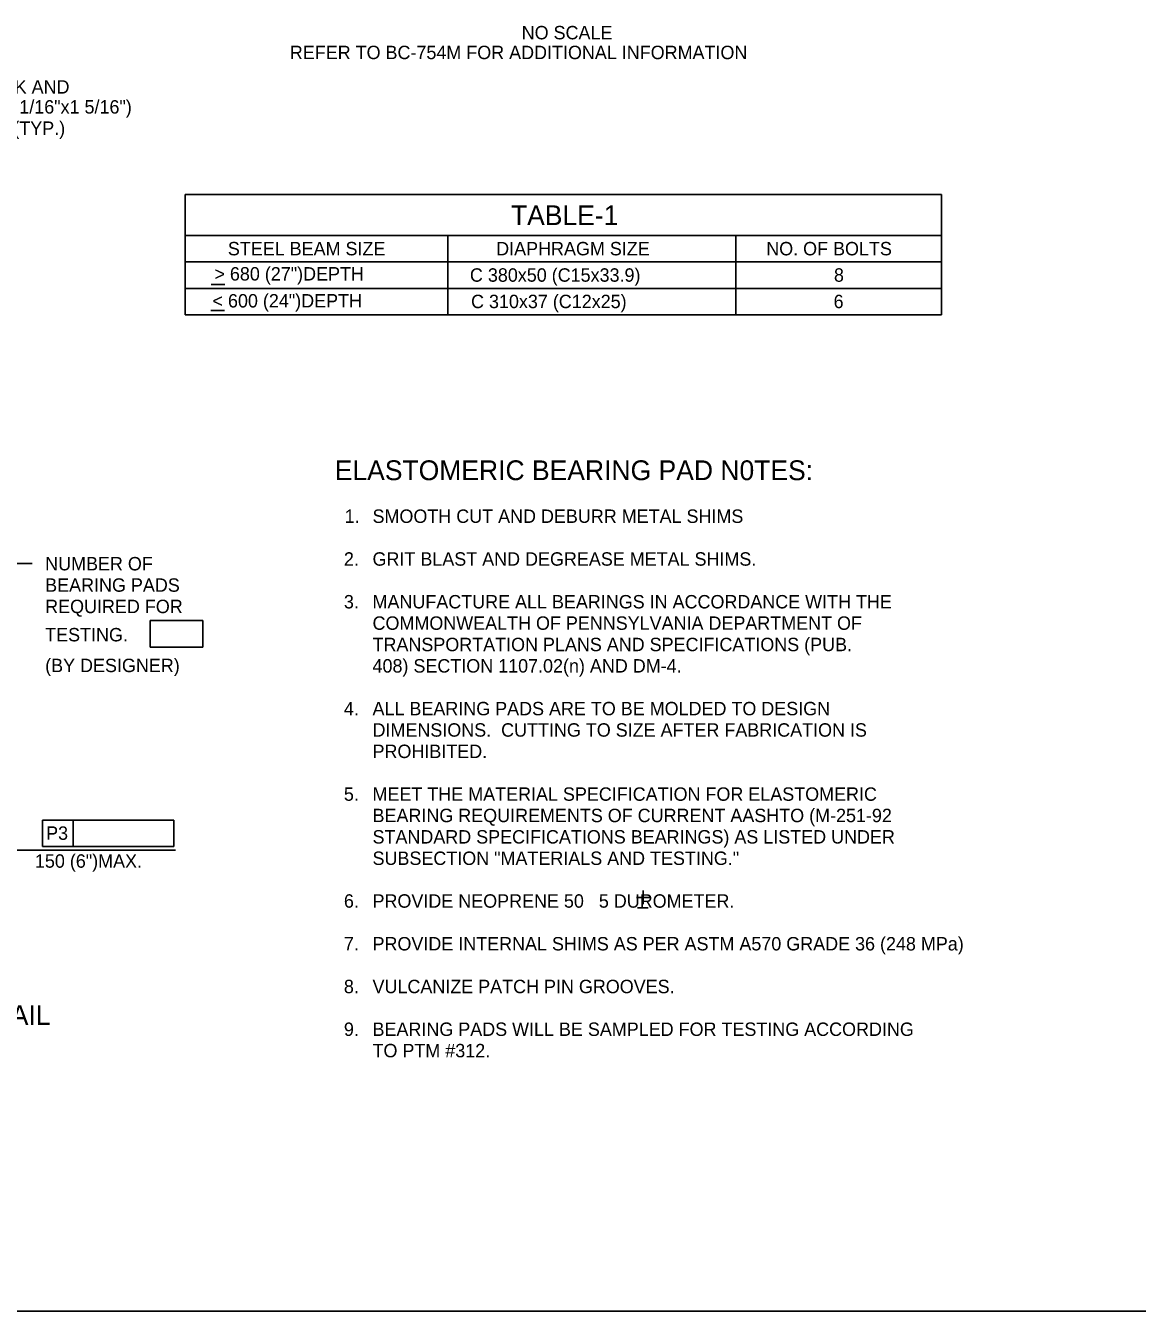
# Model space of a CAD drawing. Extents: x 638175 to 640495, y 294277 to 298435.
# Drawn here: x 639649.2 to 639897.7, y 297262.5 to 297550 of the extents above; entities that cross this region are included whole.
import ezdxf

# ---------------------------------------------------------------- set-up
doc = ezdxf.new("R2010")
doc.units = 0
doc.layers.add('2', color=7, linetype='Continuous')
doc.layers.add('3', color=7, linetype='Continuous')

msp = doc.modelspace()

# ---------------------------------------------------------------- linework, layer by layer
at = {"layer": '2'}
for p, q in [((639647.13, 297429.69), (639650.63, 297429.69)), ((640102.46, 297262.46), (639316.46, 297262.46))]:
    msp.add_line(p, q, dxfattribs=at)
at = {"layer": '3'}
for p, q in [((639684.79, 297512.2), (639853.91, 297512.2)), ((639684.79, 297512.2), (639684.79, 297485.33)), ((639853.91, 297512.2), (639853.91, 297485.33)), ((639684.79, 297503.05), (639853.91, 297503.05)), ((639743.52, 297503.05), (639743.52, 297485.33)), ((639807.93, 297503.05), (639807.93, 297485.33)), ((639684.79, 297497.14), (639853.91, 297497.14)), ((639693.71, 297492.13), (639690.63, 297492.13)), ((639684.79, 297491.24), (639853.91, 297491.24)), ((639693.64, 297486.25), (639690.56, 297486.25)), ((639684.79, 297485.33), (639853.91, 297485.33)), ((639677, 297416.92), (639688.8, 297416.92)), ((639677, 297416.92), (639677, 297411.01)), ((639688.8, 297416.92), (639688.8, 297411.01)), ((639677, 297411.01), (639688.8, 297411.01)), ((639652.89, 297372.32), (639682.29, 297372.32)), ((639652.89, 297366.42), (639652.89, 297372.32)), ((639659.74, 297366.42), (639659.74, 297372.32)), ((639682.29, 297372.32), (639682.29, 297366.42)), ((639645.02, 297365.59), (639682.68, 297365.59)), ((639682.29, 297366.42), (639652.89, 297366.42)), ((639785.72, 297355), (639788.86, 297355)), ((639787.23, 297353.49), (639787.23, 297356.57)), ((639785.96, 297352.71), (639788.31, 297352.71))]:
    msp.add_line(p, q, dxfattribs=at)

# ---------------------------------------------------------------- texts
for s, height, p in [('NO SCALE', 3, (639760.06, 297546.93)), ('REFER TO BC-754M FOR ADDITIONAL INFORMATION', 3, (639708.22, 297542.5)), ('FOR NORTHERN RED OAK AND', 3, (639597.88, 297534.8)), ('RED MAPLE.  27.0x33.3 (1 1/16"x1 5/16")', 3, (639597.78, 297530.33)), ('YELLOW POPLAR. (TYP.)', 3, (639610.05, 297525.56)), ('TABLE-1', 4.429, (639757.66, 297505.38)), ('STEEL BEAM SIZE', 3, (639694.36, 297498.62)), ('DIAPHRAGM SIZE', 3, (639754.36, 297498.62)), ('NO. OF BOLTS', 3, (639814.75, 297498.62)), ('> 680 (27")DEPTH', 3, (639691.36, 297492.99)), ('C 380x50 (C15x33.9)', 3, (639748.49, 297492.72)), ('8', 3, (639829.89, 297492.72)), ('< 600 (24")DEPTH', 3, (639690.93, 297486.96)), ('C 310x37 (C12x25)', 3, (639748.74, 297486.81)), ('6', 3, (639829.81, 297486.81)), ('ELASTOMERIC BEARING PAD N0TES:', 4.4292, (639718.26, 297448.34)), ('1.', 3, (639720.48, 297438.78)), ('SMOOTH CUT AND DEBURR METAL SHIMS', 3, (639726.71, 297438.78)), ('2.', 3, (639720.31, 297429.21)), ('GRIT BLAST AND DEGREASE METAL SHIMS.', 3, (639726.71, 297429.21)), ('NUMBER OF', 3, (639653.51, 297428.16)), ('BEARING PADS', 3, (639653.51, 297423.38)), ('REQUIRED FOR', 3, (639653.51, 297418.6)), ('3.', 3, (639720.31, 297419.65)), ('MANUFACTURE ALL BEARINGS IN ACCORDANCE WITH THE', 3, (639726.71, 297419.65)), ('COMMONWEALTH OF PENNSYLVANIA DEPARTMENT OF', 3, (639726.71, 297414.87)), ('TESTING.', 3, (639653.51, 297412.28)), ('TRANSPORTATION PLANS AND SPECIFICATIONS (PUB.', 3, (639726.71, 297410.09)), ('(BY DESIGNER)', 3, (639653.51, 297405.41)), ('408) SECTION 1107.02(n) AND DM-4.', 3, (639726.71, 297405.31)), ('4.', 3, (639720.31, 297395.75)), ('ALL BEARING PADS ARE TO BE MOLDED TO DESIGN', 3, (639726.71, 297395.75)), ('DIMENSIONS.  CUTTING TO SIZE AFTER FABRICATION IS', 3, (639726.71, 297390.97)), ('PROHIBITED.', 3, (639726.71, 297386.19)), ('5.', 3, (639720.31, 297376.63)), ('MEET THE MATERIAL SPECIFICATION FOR ELASTOMERIC', 3, (639726.71, 297376.63)), ('BEARING REQUIREMENTS OF CURRENT AASHTO (M-251-92', 3, (639726.71, 297371.85)), ('P3', 3, (639653.72, 297367.9)), ('STANDARD SPECIFICATIONS BEARINGS) AS LISTED UNDER', 3, (639726.71, 297367.07)), ('SUBSECTION "MATERIALS AND TESTING."', 3, (639726.71, 297362.28)), ('150 (6")MAX.', 3, (639651.22, 297361.66)), ('6.', 3, (639720.31, 297352.72)), ('PROVIDE NEOPRENE 50   5 DUROMETER.', 3, (639726.71, 297352.72)), ('7.', 3, (639720.31, 297343.16)), ('PROVIDE INTERNAL SHIMS AS PER ASTM A570 GRADE 36 (248 MPa)', 3, (639726.71, 297343.16)), ('8.', 3, (639720.31, 297333.6)), ('VULCANIZE PATCH PIN GROOVES.', 3, (639726.71, 297333.6)), ('EXPANSION END BEARING PAD DETAIL', 4.4292, (639541.49, 297326.48)), ('9.', 3, (639720.31, 297324.04)), ('BEARING PADS WILL BE SAMPLED FOR TESTING ACCORDING', 3, (639726.71, 297324.04)), ('TO PTM #312.', 3, (639726.71, 297319.26))]:
    msp.add_text(s, height=height, dxfattribs=at).set_placement(p)

doc.saveas('drawing.dxf')
